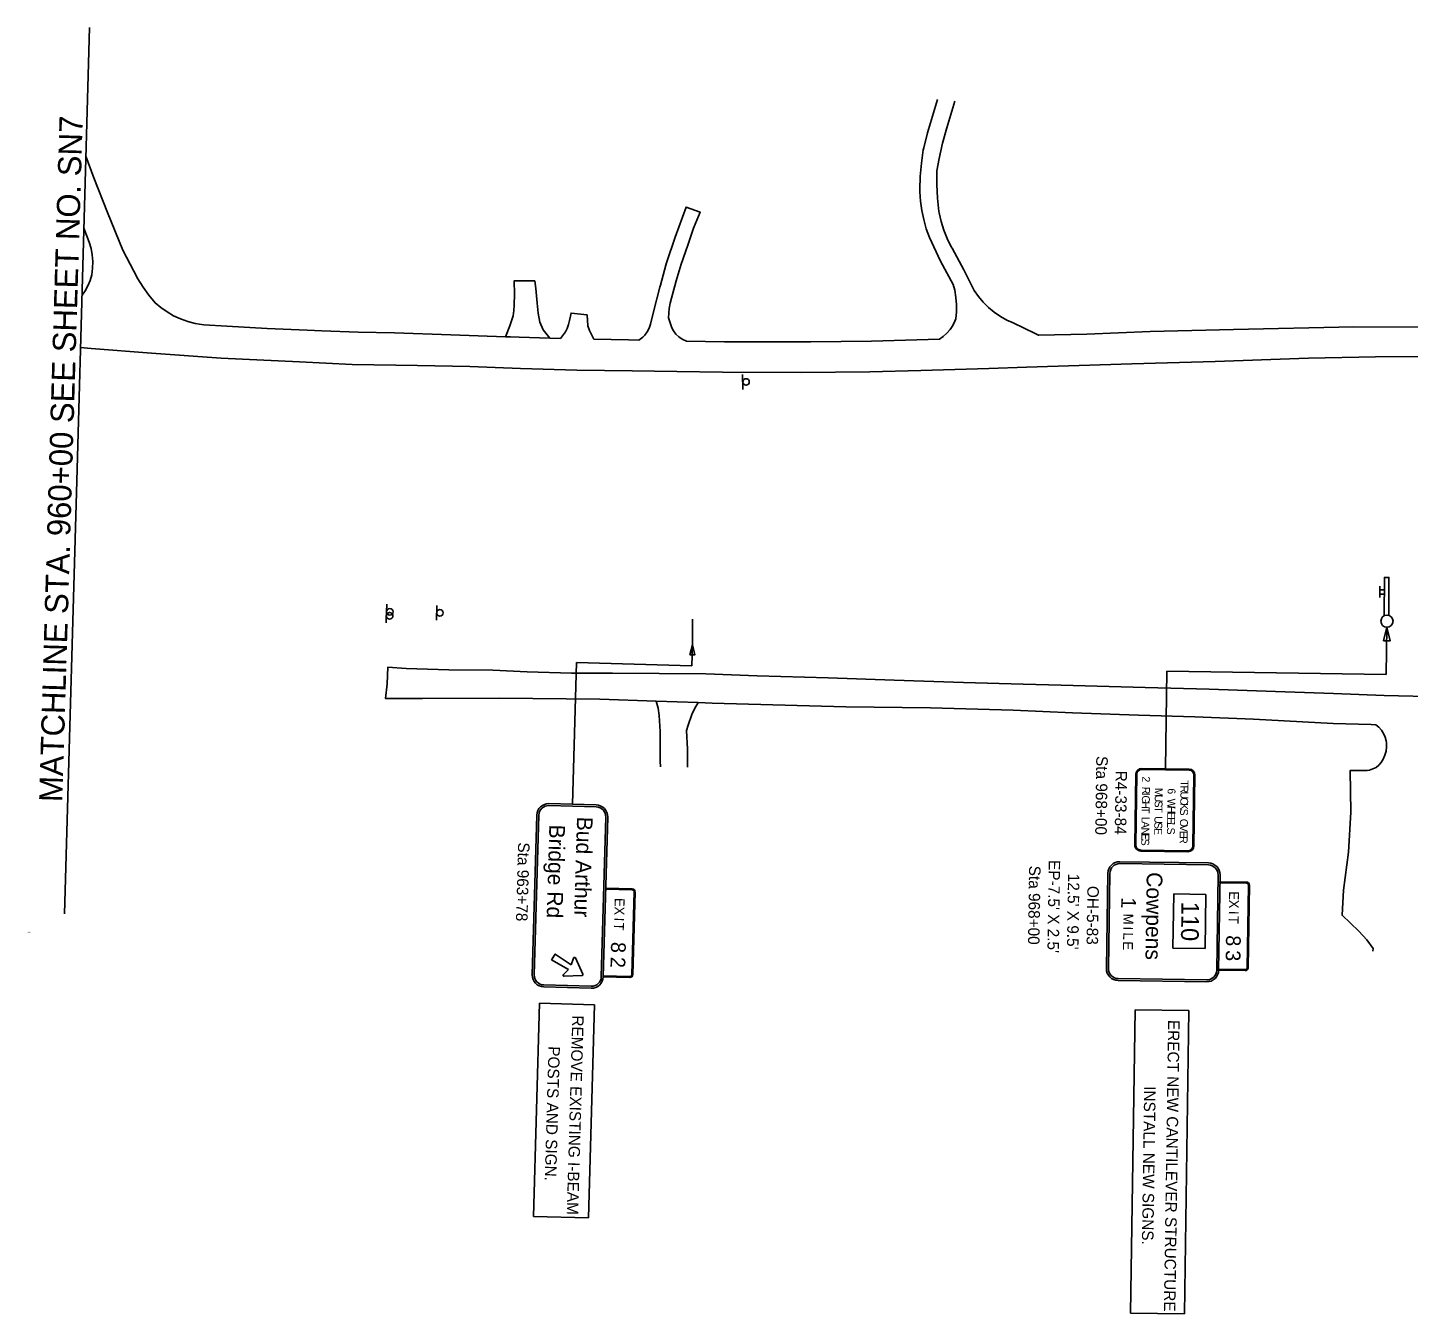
# Model space of a CAD drawing. Extents: x 1738744 to 1740331, y 1164386 to 1165340.
# Drawn here: x 1738744 to 1739586, y 1164386 to 1165170 of the extents above; entities that cross this region are included whole.
import ezdxf

# ---------------------------------------------------------------- set-up
doc = ezdxf.new("R2010")
doc.units = 0
for name, color, linetype in [('Default', 7, 'Continuous'), ('RD_EX_Driveway', 7, 'Continuous'), ('RD_EX_Road', 7, 'Continuous'), ('RD_SHT_MatchLine', 7, 'Continuous'), ('RD_SHT_TX', 7, 'Continuous'), ('SN_P_Signs', 7, 'Continuous')]:
    doc.layers.add(name, color=color, linetype=linetype)

msp = doc.modelspace()

# ---------------------------------------------------------------- linework, layer by layer
at = {"layer": 'RD_EX_Driveway'}
for points in [[(1739299.6, 1164980.42), (1739301.98, 1164982.03), (1739304.22, 1164984.01), (1739306.17, 1164986.28), (1739307.81, 1164988.77), (1739309.1, 1164991.46), (1739309.56, 1164992.7), (1739310, 1164997.07), (1739310.05, 1165001.46), (1739309.71, 1165005.84), (1739308.98, 1165010.18), (1739308.06, 1165013.75), (1739300.36, 1165027.97), (1739293.62, 1165042.34), (1739291.66, 1165047.75), (1739290.09, 1165053.27), (1739288.9, 1165058.89), (1739288.09, 1165064.58), (1739287.68, 1165070.32), (1739287.64, 1165071.57), (1739287.98, 1165079.67), (1739288.72, 1165087.74), (1739289.84, 1165095.77), (1739290.07, 1165097.14), (1739292.4, 1165106.14), (1739298.52, 1165126.45)], [(1739309.13, 1165125.45), (1739304.11, 1165109.25), (1739301.62, 1165099.95), (1739299.51, 1165090.56), (1739298.11, 1165082.99), (1739298.11, 1165074.69), (1739298.52, 1165066.41), (1739299.32, 1165058.15), (1739299.4, 1165057.48), (1739300.71, 1165052.1), (1739302.39, 1165046.82), (1739304.45, 1165041.68), (1739306.87, 1165036.69), (1739307.35, 1165035.8), (1739314.5, 1165022.67), (1739320.82, 1165010.05), (1739323.45, 1165006.36), (1739326.39, 1165002.91), (1739329.62, 1164999.73), (1739333.12, 1164996.85), (1739336.85, 1164994.28), (1739340.8, 1164992.04), (1739344.66, 1164990.27), (1739358.12, 1164983.8), (1739360.13, 1164982.79), (1739360.13, 1164982.79)], [(1739145.37, 1164979.24), (1739142.83, 1164980.44), (1739140.82, 1164981.82), (1739139.04, 1164983.51), (1739137.57, 1164985.46), (1739136.6, 1164987.24), (1739134.44, 1164993.39), (1739134.95, 1164999.13), (1739135.4, 1165002.29), (1739139.18, 1165016.05), (1739142.1, 1165026.17), (1739146.28, 1165037.69), (1739149.8, 1165048.09), (1739153.73, 1165057.87), (1739145.23, 1165060.97), (1739138.51, 1165042.55), (1739133.21, 1165026.89), (1739132.82, 1165025.45), (1739129.57, 1165013.32), (1739129.26, 1165012.18), (1739125.42, 1164997.1), (1739123.56, 1164989.49), (1739122.74, 1164987.1), (1739121.56, 1164984.87), (1739120.05, 1164982.85), (1739118.92, 1164981.68), (1739117.16, 1164980.36), (1739116.29, 1164979.87)], [(1739062.09, 1164981.04), (1739058.04, 1164986.16), (1739056.06, 1164990.81), (1739054.95, 1164996.15), (1739054.35, 1165002.31), (1739053.51, 1165011.24), (1739052.97, 1165015.96), (1739040.47, 1165015.97), (1739040.62, 1165007.9), (1739040.35, 1165001.18), (1739040.23, 1164997.93), (1739039.73, 1164994.7), (1739038.62, 1164990.89), (1739037.8, 1164988.52), (1739035.09, 1164981.9)], [(1739068.55, 1164980.85), (1739071.6, 1164984.78), (1739072.7, 1164986.9), (1739073.58, 1164989.27), (1739074.16, 1164991.83), (1739075.06, 1164996.31), (1739084.81, 1164995.14), (1739085.33, 1164988.62), (1739086.3, 1164985.76), (1739087.24, 1164983.62), (1739088.95, 1164980.38)], [(1739126.89, 1164759.62), (1739128.12, 1164755.36), (1739128.78, 1164750.88), (1739129.48, 1164741.22), (1739129.48, 1164723.03), (1739129.59, 1164719.51)], [(1739146.06, 1164719.29), (1739146.14, 1164730.43), (1739145.51, 1164741.65), (1739146.37, 1164744.99), (1739148.79, 1164751.52), (1739150.37, 1164754.95), (1739152.53, 1164758.75)]]:
    msp.add_lwpolyline(points, dxfattribs=at)
at = {"layer": 'RD_EX_Road'}
for points in [[(1739068.53, 1164980.85), (1739062.09, 1164981.04), (1739043.51, 1164981.6), (1739038.24, 1164981.79), (1739035.09, 1164981.9), (1739001.68, 1164983.01), (1738967.4, 1164984.26), (1738945.23, 1164984.62), (1738923.08, 1164985.37), (1738914.22, 1164985.78), (1738889.71, 1164986.81), (1738865.23, 1164988.22), (1738851.21, 1164989.21), (1738845.93, 1164989.9), (1738841.42, 1164991.13), (1738837.03, 1164992.73), (1738832.78, 1164994.7), (1738828.72, 1164997.02), (1738824.87, 1164999.67), (1738821.47, 1165002.45), (1738817.65, 1165007.14), (1738814.13, 1165012.07), (1738810.95, 1165017.21), (1738808.48, 1165021.79), (1738801.82, 1165034.65), (1738792.39, 1165057.7), (1738784.19, 1165078.84), (1738779.3, 1165091.9)], [(1738778.07, 1165048.11), (1738781.31, 1165039.59), (1738782.4, 1165035.7), (1738783.1, 1165031.73), (1738783.41, 1165027.71), (1738783.33, 1165023.68), (1738782.85, 1165019.67), (1738781.87, 1165016.26), (1738780.51, 1165012.99), (1738778.8, 1165009.88), (1738776.92, 1165007.21)], [(1739869.45, 1164991.06), (1739857.31, 1164990.87), (1739815.81, 1164989.91), (1739775.8, 1164989.37), (1739743.75, 1164989.21), (1739718.57, 1164989.06), (1739699.73, 1164988.86), (1739664.67, 1164988.7), (1739626.76, 1164988.4), (1739594.55, 1164987.78), (1739552.27, 1164987.92), (1739479.03, 1164986.3), (1739428.17, 1164985.09), (1739389.54, 1164983.5), (1739360.13, 1164982.79)], [(1739644.05, 1164969.79), (1739565.47, 1164969.59), (1739524.63, 1164968.74), (1739518.72, 1164968.51), (1739467.84, 1164966.76), (1739416.95, 1164965.41), (1739352.82, 1164963.31), (1739329.86, 1164962.43), (1739288.3, 1164961.18), (1739257.32, 1164960.43), (1739215.36, 1164960.03), (1739167.47, 1164960.35), (1739139.54, 1164960.58), (1739112.27, 1164961.01), (1739078.67, 1164961.57), (1739044.29, 1164962.52), (1739013.38, 1164963.7), (1738981.41, 1164964.31), (1738941.7, 1164964.99), (1738909.42, 1164966.65), (1738861.64, 1164968.86), (1738819.31, 1164971.84), (1738782.51, 1164974.68), (1738776.02, 1164975.3)], [(1739116.29, 1164979.87), (1739110.08, 1164980), (1739088.95, 1164980.38)], [(1739299.6, 1164980.42), (1739258.17, 1164979.24), (1739221.33, 1164978.74), (1739192.95, 1164978.81), (1739168.59, 1164978.8), (1739145.37, 1164979.24)], [(1739605.89, 1164762.28), (1739570.8, 1164763.18), (1739539.99, 1164764.29), (1739504.53, 1164765.48), (1739464.19, 1164767.05), (1739425.18, 1164767.94), (1739373.81, 1164769.4), (1739350.68, 1164770.02), (1739314.32, 1164771.06), (1739272.02, 1164772.48), (1739231.82, 1164773.82), (1739188.57, 1164775.08), (1739157.23, 1164776.32), (1739100.32, 1164776.79), (1739075.39, 1164776.65), (1739048.21, 1164777.55), (1739027.29, 1164778.57), (1739000.56, 1164778.79), (1738974.5, 1164779.53), (1738963.32, 1164780.29), (1738962.87, 1164770.25), (1738962.03, 1164761.24), (1738984.58, 1164761.3), (1739031.16, 1164761.43), (1739092.63, 1164760.78), (1739126.89, 1164759.62), (1739152.53, 1164758.75), (1739161.11, 1164758.46), (1739242.68, 1164756.22), (1739294.23, 1164755.53), (1739344.51, 1164754.23), (1739380.84, 1164752.59), (1739420.93, 1164751.11), (1739455.36, 1164750.1), (1739491.04, 1164748.66), (1739539.81, 1164746.03), (1739562.92, 1164745.34), (1739565.64, 1164745.17), (1739565.68, 1164745.17)], [(1739565.64, 1164745.17), (1739567.55, 1164743.68), (1739569.17, 1164741.94), (1739570.47, 1164739.95), (1739571.43, 1164737.77), (1739572.01, 1164735.46), (1739572.15, 1164734.4), (1739572.26, 1164731.79), (1739571.97, 1164729.19), (1739571.3, 1164726.66), (1739570.25, 1164724.27), (1739568.96, 1164722.2), (1739567.54, 1164720.59), (1739565.84, 1164719.26), (1739563.94, 1164718.27), (1739561.88, 1164717.64), (1739560.36, 1164717.43), (1739550.14, 1164717.43), (1739550.46, 1164691.87), (1739548.99, 1164667.57), (1739546, 1164644.43), (1739545.18, 1164629.1), (1739555.42, 1164619.37), (1739560.19, 1164614.16), (1739564.17, 1164608.78), (1739563.96, 1164607.28)]]:
    msp.add_lwpolyline(points, dxfattribs=at)
at = {"layer": 'RD_SHT_MatchLine'}
msp.add_lwpolyline([(1738766.3, 1164630.02), (1738773.73, 1164894.04), (1738781.51, 1165170.38)], dxfattribs=at)
at = {"layer": 'SN_P_Signs'}
for p, q in [((1739179.66, 1164958.78), (1739179.8, 1164949.78)), ((1739570.9, 1164827.58), (1739568.12, 1164827.59)), ((1739570.9, 1164824.9), (1739568.13, 1164824.91)), ((1739568.14, 1164822.81), (1739568.15, 1164829.77)), ((1738962.61, 1164816.33), (1738962.25, 1164807.33)), ((1738962.71, 1164818.69), (1738962.35, 1164809.7)), ((1738993.21, 1164818.04), (1738993.03, 1164809.04)), ((1739149.13, 1164793.98), (1739149.15, 1164809.67)), ((1739572.08, 1164775.88), (1739572.45, 1164804.7)), ((1739149.13, 1164793.98), (1739148.77, 1164781.19)), ((1739078.44, 1164783.17), (1739076.01, 1164696.76)), ((1739148.77, 1164781.19), (1739078.44, 1164783.17)), ((1739438.35, 1164777.84), (1739437.48, 1164718.45)), ((1739438.35, 1164777.84), (1739572.08, 1164775.88)), ((1739052.12, 1164445.46), (1739055.78, 1164575.43)), ((1739055.78, 1164575.43), (1739089.39, 1164574.49)), ((1739089.39, 1164574.49), (1739085.73, 1164444.52)), ((1739416.22, 1164386.47), (1739418.93, 1164571.4)), ((1739418.93, 1164571.4), (1739451.73, 1164570.92)), ((1739451.73, 1164570.92), (1739449.02, 1164385.99)), ((1739085.73, 1164444.52), (1739052.12, 1164445.46)), ((1739449.02, 1164385.99), (1739416.22, 1164386.47))]:
    msp.add_line(p, q, dxfattribs=at)
for points in [[(1739573.67, 1164811.93), (1739573.71, 1164835.06), (1739570.92, 1164835.06), (1739570.88, 1164811.75)], [(1739419.43, 1164715.11), (1739418.8, 1164671.92)], [(1739420.03, 1164715.1), (1739419.4, 1164671.91)], [(1739451.87, 1164717.64), (1739423.08, 1164718.06)], [(1739451.88, 1164718.24), (1739423.09, 1164718.66)], [(1739454.2, 1164671.4), (1739454.83, 1164714.59)], [(1739454.8, 1164671.39), (1739455.43, 1164714.58)], [(1739061.54, 1164695.96), (1739090.41, 1164695.15)], [(1739061.58, 1164697.16), (1739090.45, 1164696.35)], [(1739051.44, 1164592.8), (1739054.18, 1164690.17)], [(1739052.64, 1164592.76), (1739055.38, 1164690.14)], [(1739096.24, 1164688.99), (1739093.5, 1164591.61)], [(1739097.44, 1164688.95), (1739094.7, 1164591.58)], [(1739422.35, 1164668.26), (1739451.14, 1164667.84)], [(1739422.36, 1164668.86), (1739451.15, 1164668.44)], [(1739401.5, 1164596.55), (1739402.35, 1164654.66)], [(1739402.7, 1164596.53), (1739403.55, 1164654.64)], [(1739409.63, 1164660.55), (1739463.63, 1164659.76)], [(1739409.65, 1164661.75), (1739463.65, 1164660.96)], [(1739469.54, 1164653.67), (1739468.69, 1164595.57)], [(1739470.74, 1164653.66), (1739469.89, 1164595.55)], [(1739112.4, 1164644.5), (1739096.2, 1164644.96), (1739096.22, 1164645.56), (1739112.41, 1164645.1)], [(1739486.87, 1164648.71), (1739470.67, 1164648.94), (1739470.68, 1164649.54), (1739486.88, 1164649.31)], [(1739487.31, 1164597.09), (1739488.05, 1164647.49)], [(1739488.65, 1164647.48), (1739487.91, 1164597.09)], [(1739112.14, 1164592.89), (1739113.56, 1164643.27)], [(1739114.16, 1164643.25), (1739112.74, 1164592.87)], [(1739442, 1164609.04), (1739442.48, 1164642.11)], [(1739442.48, 1164642.11), (1739462.17, 1164641.82)], [(1739462.17, 1164641.82), (1739461.69, 1164608.75)], [(1739063.19, 1164601.82), (1739065.39, 1164605.4), (1739075.23, 1164598.77)], [(1739075.23, 1164598.77), (1739076.62, 1164603)], [(1739077.73, 1164603.06), (1739082.21, 1164593.17)], [(1739461.69, 1164608.75), (1739442, 1164609.04)], [(1739073.54, 1164596.03), (1739063.19, 1164601.82)], [(1739070.39, 1164592.89), (1739073.54, 1164596.03)], [(1739486.09, 1164595.31), (1739469.89, 1164595.55), (1739469.9, 1164596.15)], [(1739469.9, 1164596.15), (1739486.1, 1164595.91)], [(1739087.34, 1164585.78), (1739058.47, 1164586.6)], [(1739081.69, 1164592.32), (1739070.84, 1164591.86)], [(1739110.89, 1164591.12), (1739094.7, 1164591.58), (1739094.72, 1164592.18)], [(1739094.72, 1164592.18), (1739110.91, 1164591.72)], [(1739462.58, 1164588.46), (1739408.59, 1164589.25)], [(1739462.6, 1164589.66), (1739408.61, 1164590.45)], [(1739087.3, 1164584.58), (1739058.43, 1164585.4)]]:
    msp.add_lwpolyline(points, dxfattribs=at)
for points in [[(1739570.43, 1164796.5), (1739572.49, 1164804.7), (1739574.53, 1164796.49)], [(1739147.42, 1164787.87), (1739149.13, 1164793.98), (1739150.49, 1164787.79)]]:
    msp.add_lwpolyline(points, close=True, dxfattribs=at)
for centre, radius in [((1739181.75, 1164954.29), 2), ((1738964.46, 1164811.73), 2), ((1738964.55, 1164814.1), 2), ((1738995.14, 1164813.48), 2), ((1739572.5, 1164808.41), 3.71)]:
    msp.add_circle(centre, radius, dxfattribs=at)
for centre, radius, start, end in [((1739423.03, 1164715.06), 3.6, 89.16122, 179.16122), ((1739423.03, 1164715.06), 3, 89.16122, 179.16122), ((1739451.83, 1164714.64), 3, 359.16122, 89.16122), ((1739451.83, 1164714.64), 3.6, 359.16122, 89.16122), ((1739061.38, 1164689.97), 7.2, 88.38781, 178.38781), ((1739061.38, 1164689.97), 6, 88.38781, 178.38781), ((1739090.24, 1164689.15), 7.2, 358.38781, 88.38781), ((1739090.24, 1164689.15), 6, 358.38781, 88.38781), ((1739422.4, 1164671.86), 3.6, 179.16122, 269.16122), ((1739422.4, 1164671.86), 3, 179.16122, 269.16122), ((1739451.2, 1164671.44), 3.6, 269.16122, 359.16122), ((1739451.2, 1164671.44), 3, 269.16122, 359.16122), ((1739409.55, 1164654.55), 7.2, 89.16122, 179.16122), ((1739409.55, 1164654.55), 6, 89.16122, 179.16122), ((1739463.54, 1164653.76), 6, 359.16122, 89.16122), ((1739463.54, 1164653.76), 7.2, 359.16122, 89.16122), ((1739112.36, 1164643.3), 1.8, 358.38781, 88.38781), ((1739486.85, 1164647.51), 1.2, 359.16122, 89.16122), ((1739486.85, 1164647.51), 1.8, 359.16122, 89.16122), ((1739112.36, 1164643.3), 1.2, 358.38781, 88.38781), ((1739077.19, 1164602.81), 0.6, 24.36851, 161.83391), ((1739408.69, 1164596.45), 7.2, 179.16122, 269.16122), ((1739408.69, 1164596.45), 6, 179.16122, 269.16122), ((1739462.69, 1164595.66), 7.2, 269.16122, 359.16122), ((1739462.69, 1164595.66), 6, 269.16122, 359.16122), ((1739486.11, 1164597.11), 1.8, 269.16122, 359.16122), ((1739486.11, 1164597.11), 1.2, 269.16122, 359.16122), ((1739058.64, 1164592.59), 7.2, 178.38781, 268.38781), ((1739058.64, 1164592.59), 6, 178.38781, 268.38781), ((1739070.82, 1164592.46), 0.6, 134.94171, 272.40721), ((1739081.67, 1164592.92), 0.6, 272.40721, 24.36851), ((1739087.5, 1164591.78), 7.2, 268.38781, 358.38781), ((1739087.5, 1164591.78), 6, 268.38781, 358.38781), ((1739110.95, 1164592.92), 1.8, 268.38781, 358.38781), ((1739110.95, 1164592.92), 1.2, 268.38781, 358.38781)]:
    msp.add_arc(centre, radius, start, end, dxfattribs=at)

# ---------------------------------------------------------------- texts
at = {"layer": 'Default'}
for s, height, p in [('Angle:  17.6970', 0.2083, (1738743.73, 1164618.56)), ('Align: A_I85', 0.2083, (1738743.73, 1164618.29)), ('Sheet: 8', 0.208, (1738743.73, 1164618.83))]:
    msp.add_text(s, height=height, dxfattribs=at).set_placement(p)
at = {"layer": 'RD_SHT_TX'}
msp.add_text('MATCHLINE STA. 960+00 SEE SHEET NO. SN7', height=14.1726, rotation=88.28705, dxfattribs=at).set_placement((1738764.88, 1164697.95))
at = {"layer": 'SN_P_Signs'}
for s, height, rotation, p in [('Sta 968+00', 7, 269.1613, (1739395.32, 1164726.22)), ('R4-33-84', 7, 269.1613, (1739407.09, 1164717.28)), ('2', 4.8, 269.16122, (1739423.31, 1164713.74)), ('R', 4.8, 269.16122, (1739423.22, 1164707.52)), ('M', 4.8, 269.16122, (1739431.01, 1164706.77)), ('6', 4.8, 269.16122, (1739438.81, 1164706.49)), ('U', 4.8, 269.16122, (1739446.58, 1164704.63)), ('R', 4.8, 269.16122, (1739446.64, 1164708.27)), ('T', 4.8, 269.16122, (1739446.68, 1164711.48)), ('G', 4.8, 269.16122, (1739423.14, 1164702.19)), ('H', 4.8, 269.16122, (1739423.09, 1164698.56)), ('I', 4.8, 269.16122, (1739423.17, 1164703.88)), ('S', 4.8, 269.16122, (1739430.9, 1164699.02)), ('U', 4.8, 269.16122, (1739430.95, 1164702.65)), ('W', 4.8, 269.16122, (1739438.72, 1164700.27)), ('C', 4.8, 269.16122, (1739446.53, 1164701)), ('K', 4.8, 269.16122, (1739446.48, 1164697.56)), ('Bud Arthur', 9.6, 268.38781, (1739078.7, 1164689.25)), ('L', 4.8, 269.16122, (1739422.95, 1164689.13)), ('T', 4.8, 269.16122, (1739423.04, 1164695.12)), ('U', 4.8, 269.16122, (1739430.76, 1164689.58)), ('T', 4.8, 269.16122, (1739430.85, 1164695.58)), ('E', 4.8, 269.16122, (1739438.55, 1164689.01)), ('E', 4.8, 269.16122, (1739438.6, 1164692.22)), ('H', 4.8, 269.16122, (1739438.65, 1164695.86)), ('O', 4.8, 269.16122, (1739446.34, 1164687.9)), ('S', 4.8, 269.16122, (1739446.43, 1164694.13)), ('Bridge Rd', 9.6, 268.38781, (1739061.82, 1164684.47)), ('N', 4.8, 269.16122, (1739422.86, 1164682.64)), ('A', 4.8, 269.16122, (1739422.91, 1164686.45)), ('S', 4.8, 269.16122, (1739430.71, 1164685.95)), ('E', 4.8, 269.16122, (1739430.65, 1164682.31)), ('S', 4.8, 269.16122, (1739438.46, 1164682.59)), ('L', 4.8, 269.16122, (1739438.51, 1164685.8)), ('E', 4.8, 269.16122, (1739446.23, 1164680.58)), ('V', 4.8, 269.16122, (1739446.29, 1164684.32)), ('Sta 963+78', 7, 268.38789, (1739042.82, 1164673.58)), ('S', 4.8, 269.16122, (1739422.76, 1164675.8)), ('E', 4.8, 269.16122, (1739422.81, 1164679.01)), ('R', 4.8, 269.16122, (1739446.18, 1164677.37)), ("EP-7.5' X 2.5'", 7, 269.1613, (1739366.29, 1164662.79)), ('Sta 968+00', 7, 269.1613, (1739354.34, 1164659.33)), ("12.5' X 9.5'", 7, 269.1613, (1739378.07, 1164654.46)), ('Cowpens', 9.6, 269.16122, (1739426.06, 1164655.41)), ('OH-5-83', 7, 269.1613, (1739389.86, 1164647.01)), ('E', 6, 268.38781, (1739101.76, 1164639.67)), ('1', 9, 269.16122, (1739410.53, 1164640.04)), ('X', 6, 269.16122, (1739476.22, 1164638.58)), ('E', 6, 269.16122, (1739476.29, 1164643.73)), ('X', 6, 268.38781, (1739101.61, 1164634.52)), ('M', 6, 269.16122, (1739411.89, 1164630.08)), ('110', 10.8, 269.16122, (1739447.25, 1164637.44)), ('T', 6, 269.16122, (1739476.08, 1164628.78)), ('I', 6, 269.16122, (1739476.12, 1164631.76)), ('T', 6, 268.38781, (1739101.34, 1164624.72)), ('I', 6, 268.38781, (1739101.42, 1164627.7)), ('I', 6, 269.16122, (1739411.77, 1164622.22)), ('8', 9, 268.38781, (1739099.5, 1164612.9)), ('E', 6, 269.16122, (1739411.64, 1164613.2)), ('L', 6, 269.16122, (1739411.72, 1164618.63)), ('8', 9, 269.16122, (1739474.4, 1164616.93)), ('2', 9, 268.38781, (1739099.25, 1164603.8)), ('3', 9, 269.16122, (1739474.27, 1164607.83)), ('REMOVE EXISTING I-BEAM', 7, 268.38789, (1739075.84, 1164568.11)), ('ERECT NEW CANTILEVER STRUCTURE.', 7, 269.1613, (1739439.1, 1164565.29)), ('POSTS AND SIGN.', 7, 268.38789, (1739061.3, 1164549.28)), ('INSTALL NEW SIGNS.', 7, 269.1613, (1739424.5, 1164524.87))]:
    msp.add_text(s, height=height, rotation=rotation, dxfattribs=at).set_placement(p)

doc.saveas('drawing.dxf')
